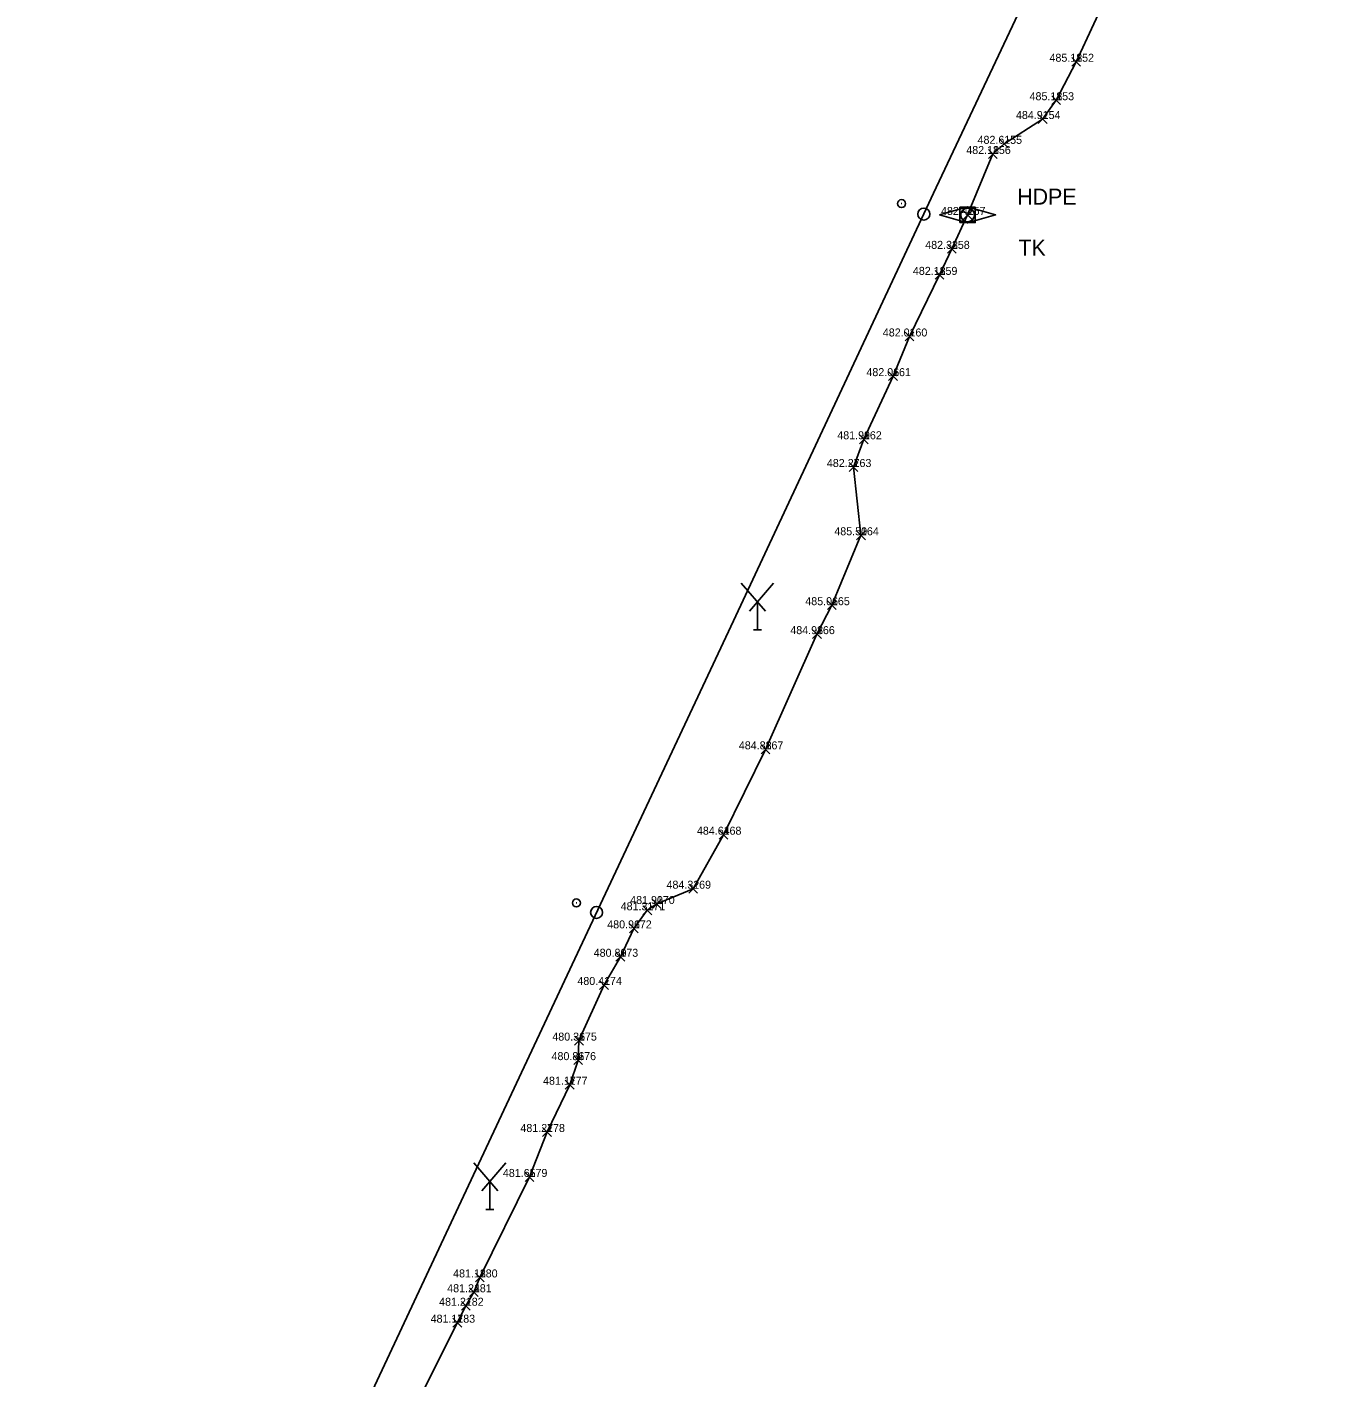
# Model space of a CAD drawing. Extents: x -874058 to -854960, y -10531873 to -1049126.
# Drawn here: x -867097.5 to -866933, y -1051112.9 to -1050944.1 of the extents above; entities that cross this region are included whole.
import ezdxf

# ---------------------------------------------------------------- set-up
doc = ezdxf.new("R2010")
doc.units = 0
for name, color, linetype in [('Vrstva 1', 7, 'Continuous'), ('Vrstva 30', 7, 'Continuous'), ('Vrstva 32', 7, 'Continuous'), ('Vrstva 4', 7, 'Continuous'), ('Vrstva 60', 7, 'Continuous'), ('Vrstva 61', 7, 'Continuous'), ('Vrstva 7', 7, 'Continuous')]:
    doc.layers.add(name, color=color, linetype=linetype)

msp = doc.modelspace()

# ---------------------------------------------------------------- linework, layer by layer
at = {"layer": 'Vrstva 1'}
for points in [[(-866933.01, -1050862.67), (-866940.75, -1050875.77), (-866947.17, -1050887.44), (-866955.62, -1050904.28), (-866971.87, -1050938.69), (-866984.17, -1050964.88), (-867009.17, -1051018.35), (-867029.98, -1051062.63)], [(-867029.98, -1051062.63), (-867042.91, -1051090.26), (-867056.79, -1051119.87), (-867068.56, -1051145.98), (-867073.25, -1051157.39), (-867081.41, -1051178.88), (-867087.54, -1051197.13), (-867097.47, -1051229.63)]]:
    msp.add_lwpolyline(points, dxfattribs=at)
at = {"layer": 'Vrstva 30'}
msp.add_lwpolyline([(-866980.88, -1050968.56), (-866978.96, -1050968.56), (-866978.96, -1050966.64), (-866980.88, -1050966.64)], close=True, dxfattribs=at)
msp.add_circle((-866979.92, -1050967.6), 0.864, dxfattribs=at)
at = {"layer": 'Vrstva 32'}
for points in [[(-866940.2, -1050885.9), (-866947.62, -1050904.69), (-866957.11, -1050927.47), (-866961.94, -1050938.9), (-866966.36, -1050948.45), (-866968.85, -1050953.26), (-866970.55, -1050955.61), (-866975.35, -1050958.71), (-866976.76, -1050959.98), (-866979.92, -1050967.6)], [(-866983.42, -1050967.6), (-866979.92, -1050966.6), (-866976.42, -1050967.6), (-866979.92, -1050968.6), (-866983.42, -1050967.6)], [(-867050.73, -1051120.11), (-867043.7, -1051106.07), (-867042.64, -1051103.95), (-867041.63, -1051102.26), (-867040.89, -1051100.41), (-867034.67, -1051087.85), (-867032.48, -1051082.23), (-867029.65, -1051076.32), (-867028.59, -1051073.25), (-867028.49, -1051070.81), (-867025.36, -1051063.85), (-867023.32, -1051060.33), (-867021.63, -1051056.78), (-867019.95, -1051054.52), (-867018.76, -1051053.73), (-867014.22, -1051051.82), (-867010.42, -1051045.07), (-867005.18, -1051034.4), (-866998.75, -1051020), (-866996.88, -1051016.38), (-866993.25, -1051007.64), (-866994.18, -1050999.11), (-866992.88, -1050995.64), (-866989.24, -1050987.75), (-866987.19, -1050982.79), (-866983.43, -1050975.09), (-866981.89, -1050971.84), (-866979.92, -1050967.6)]]:
    msp.add_lwpolyline(points, dxfattribs=at)
at = {"layer": 'Vrstva 4'}
for p, q in [((-867008.2, -1051013.63), (-867005.2, -1051017.13)), ((-867007.2, -1051017.13), (-867004.2, -1051013.63)), ((-867006.2, -1051019.48), (-867006.2, -1051015.98)), ((-867006.7, -1051019.48), (-867005.7, -1051019.48)), ((-867041.65, -1051086.09), (-867038.65, -1051089.59)), ((-867040.65, -1051089.59), (-867037.65, -1051086.09)), ((-867039.65, -1051091.94), (-867039.65, -1051088.44)), ((-867040.15, -1051091.94), (-867039.15, -1051091.94))]:
    msp.add_line(p, q, dxfattribs=at)
at = {"layer": 'Vrstva 60'}
for p, q in [((-866966.91, -1050949), (-866965.81, -1050947.9)), ((-866965.81, -1050949), (-866966.91, -1050947.9)), ((-866969.4, -1050953.81), (-866968.3, -1050952.71)), ((-866968.3, -1050953.81), (-866969.4, -1050952.71)), ((-866971.1, -1050956.16), (-866970, -1050955.06)), ((-866970, -1050956.16), (-866971.1, -1050955.06)), ((-866975.9, -1050959.26), (-866974.8, -1050958.16)), ((-866974.8, -1050959.26), (-866975.9, -1050958.16)), ((-866977.31, -1050960.53), (-866976.21, -1050959.43)), ((-866976.21, -1050960.53), (-866977.31, -1050959.43)), ((-866980.47, -1050968.15), (-866979.37, -1050967.05)), ((-866979.37, -1050968.15), (-866980.47, -1050967.05)), ((-866982.44, -1050972.39), (-866981.34, -1050971.29)), ((-866981.34, -1050972.39), (-866982.44, -1050971.29)), ((-866983.98, -1050975.64), (-866982.88, -1050974.54)), ((-866982.88, -1050975.64), (-866983.98, -1050974.54)), ((-866987.74, -1050983.34), (-866986.64, -1050982.24)), ((-866986.64, -1050983.34), (-866987.74, -1050982.24)), ((-866989.79, -1050988.3), (-866988.69, -1050987.2)), ((-866988.69, -1050988.3), (-866989.79, -1050987.2)), ((-866993.43, -1050996.19), (-866992.33, -1050995.09)), ((-866992.33, -1050996.19), (-866993.43, -1050995.09)), ((-866994.73, -1050999.66), (-866993.63, -1050998.56)), ((-866993.63, -1050999.66), (-866994.73, -1050998.56)), ((-866993.8, -1051008.19), (-866992.7, -1051007.09)), ((-866992.7, -1051008.19), (-866993.8, -1051007.09)), ((-866997.43, -1051016.93), (-866996.33, -1051015.83)), ((-866996.33, -1051016.93), (-866997.43, -1051015.83)), ((-866999.3, -1051020.55), (-866998.2, -1051019.45)), ((-866998.2, -1051020.55), (-866999.3, -1051019.45)), ((-867005.73, -1051034.95), (-867004.63, -1051033.85)), ((-867004.63, -1051034.95), (-867005.73, -1051033.85)), ((-867010.97, -1051045.62), (-867009.87, -1051044.52)), ((-867009.87, -1051045.62), (-867010.97, -1051044.52)), ((-867014.77, -1051052.37), (-867013.67, -1051051.27)), ((-867013.67, -1051052.37), (-867014.77, -1051051.27)), ((-867019.31, -1051054.28), (-867018.21, -1051053.18)), ((-867018.21, -1051054.28), (-867019.31, -1051053.18)), ((-867020.5, -1051055.07), (-867019.4, -1051053.97)), ((-867019.4, -1051055.07), (-867020.5, -1051053.97)), ((-867022.18, -1051057.33), (-867021.08, -1051056.23)), ((-867021.08, -1051057.33), (-867022.18, -1051056.23)), ((-867023.87, -1051060.88), (-867022.77, -1051059.78)), ((-867022.77, -1051060.88), (-867023.87, -1051059.78)), ((-867025.91, -1051064.4), (-867024.81, -1051063.3)), ((-867024.81, -1051064.4), (-867025.91, -1051063.3)), ((-867029.04, -1051071.36), (-867027.94, -1051070.26)), ((-867027.94, -1051071.36), (-867029.04, -1051070.26)), ((-867029.14, -1051073.8), (-867028.04, -1051072.7)), ((-867028.04, -1051073.8), (-867029.14, -1051072.7)), ((-867030.2, -1051076.87), (-867029.1, -1051075.77)), ((-867029.1, -1051076.87), (-867030.2, -1051075.77)), ((-867033.03, -1051082.78), (-867031.93, -1051081.68)), ((-867031.93, -1051082.78), (-867033.03, -1051081.68)), ((-867035.22, -1051088.4), (-867034.12, -1051087.3)), ((-867034.12, -1051088.4), (-867035.22, -1051087.3)), ((-867041.44, -1051100.96), (-867040.34, -1051099.86)), ((-867040.34, -1051100.96), (-867041.44, -1051099.86)), ((-867042.18, -1051102.81), (-867041.08, -1051101.71)), ((-867041.08, -1051102.81), (-867042.18, -1051101.71)), ((-867043.19, -1051104.5), (-867042.09, -1051103.4)), ((-867042.09, -1051104.5), (-867043.19, -1051103.4)), ((-867044.25, -1051106.62), (-867043.15, -1051105.52)), ((-867043.15, -1051106.62), (-867044.25, -1051105.52))]:
    msp.add_line(p, q, dxfattribs=at)
at = {"layer": 'Vrstva 7'}
for p, q in [((-866988.23, -1050966.18), (-866988.13, -1050966.18)), ((-867028.86, -1051053.6), (-867028.76, -1051053.6))]:
    msp.add_line(p, q, dxfattribs=at)
for centre, radius in [((-866988.18, -1050966.18), 0.5), ((-866985.39, -1050967.49), 0.75), ((-867028.81, -1051053.6), 0.5), ((-867026.29, -1051054.78), 0.75)]:
    msp.add_circle(centre, radius, dxfattribs=at)

# ---------------------------------------------------------------- texts
at = {"layer": 'Vrstva 32'}
for s, p in [('HDPE', (-866973.73, -1050966.31)), ('TK', (-866973.58, -1050972.69))]:
    msp.add_text(s, height=2, dxfattribs=at).set_placement(p)
at = {"layer": 'Vrstva 60'}
for s, p in [('152', (-866966.36, -1050948.45)), ('153', (-866968.85, -1050953.26)), ('154', (-866970.55, -1050955.61)), ('155', (-866975.35, -1050958.71)), ('156', (-866976.76, -1050959.98)), ('157', (-866979.92, -1050967.6)), ('158', (-866981.89, -1050971.84)), ('159', (-866983.43, -1050975.09)), ('160', (-866987.19, -1050982.79)), ('161', (-866989.24, -1050987.75)), ('162', (-866992.88, -1050995.64)), ('163', (-866994.18, -1050999.11)), ('164', (-866993.25, -1051007.64)), ('165', (-866996.88, -1051016.38)), ('166', (-866998.75, -1051020)), ('167', (-867005.18, -1051034.4)), ('168', (-867010.42, -1051045.07)), ('169', (-867014.22, -1051051.82)), ('170', (-867018.76, -1051053.73)), ('171', (-867019.95, -1051054.52)), ('172', (-867021.63, -1051056.78)), ('173', (-867023.32, -1051060.33)), ('174', (-867025.36, -1051063.85)), ('175', (-867028.49, -1051070.81)), ('176', (-867028.59, -1051073.25)), ('177', (-867029.65, -1051076.32)), ('178', (-867032.48, -1051082.23)), ('179', (-867034.67, -1051087.85)), ('180', (-867040.89, -1051100.41)), ('181', (-867041.63, -1051102.26)), ('182', (-867042.64, -1051103.95)), ('183', (-867043.7, -1051106.07))]:
    msp.add_text(s, height=1, dxfattribs=at).set_placement(p)
at = {"layer": 'Vrstva 61'}
for s, p in [('485.18 ', (-866969.69, -1050948.45)), ('485.18 ', (-866972.18, -1050953.26)), ('484.91 ', (-866973.88, -1050955.61)), ('482.61 ', (-866978.68, -1050958.71)), ('482.18 ', (-866980.09, -1050959.98)), ('482.41 ', (-866983.25, -1050967.6)), ('482.33 ', (-866985.22, -1050971.84)), ('482.18 ', (-866986.76, -1050975.09)), ('482.01 ', (-866990.52, -1050982.79)), ('482.06 ', (-866992.57, -1050987.75)), ('481.99 ', (-866996.21, -1050995.64)), ('482.27 ', (-866997.51, -1050999.11)), ('485.50 ', (-866996.58, -1051007.64)), ('485.06 ', (-867000.21, -1051016.38)), ('484.98 ', (-867002.08, -1051020)), ('484.88 ', (-867008.51, -1051034.4)), ('484.64 ', (-867013.75, -1051045.07)), ('484.32 ', (-867017.55, -1051051.82)), ('481.90 ', (-867022.09, -1051053.73)), ('481.31 ', (-867023.28, -1051054.52)), ('480.96 ', (-867024.96, -1051056.78)), ('480.80 ', (-867026.65, -1051060.33)), ('480.41 ', (-867028.69, -1051063.85)), ('480.36 ', (-867031.82, -1051070.81)), ('480.86 ', (-867031.92, -1051073.25)), ('481.17 ', (-867032.98, -1051076.32)), ('481.27 ', (-867035.81, -1051082.23)), ('481.65 ', (-867038, -1051087.85)), ('481.18 ', (-867044.22, -1051100.41)), ('481.24 ', (-867044.96, -1051102.26)), ('481.21 ', (-867045.97, -1051103.95)), ('481.17 ', (-867047.03, -1051106.07))]:
    msp.add_text(s, height=1, dxfattribs=at).set_placement(p)

doc.saveas('drawing.dxf')
